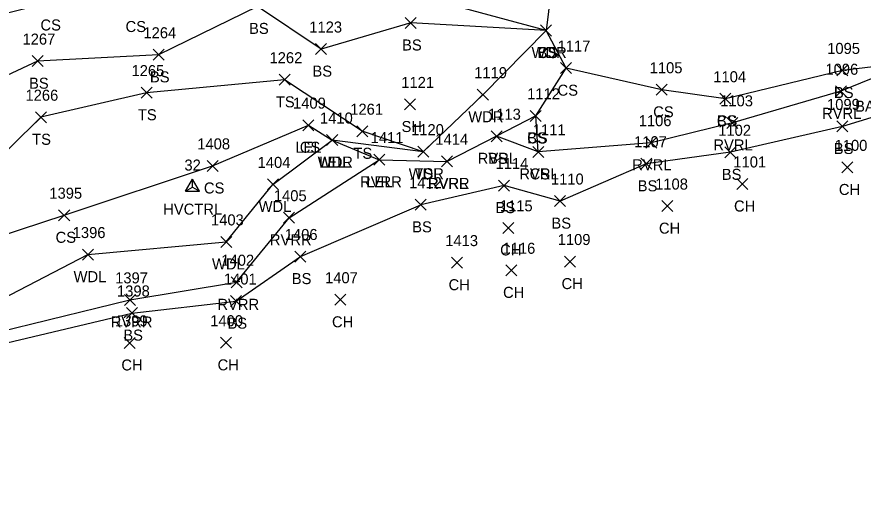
# Model space of a CAD drawing. Extents: x 1502119 to 1504100, y 606168 to 606406.
# Drawn here: x 1503856.3 to 1504009.8, y 606184.3 to 606269.9 of the extents above; entities that cross this region are included whole.
import ezdxf

# ---------------------------------------------------------------- set-up
doc = ezdxf.new("R2010")
doc.units = 0
for name, color, linetype in [('C_A', 7, 'Continuous'), ('C_I', 7, 'Continuous'), ('CPSM', 7, 'Continuous'), ('L_A', 7, 'Continuous'), ('L_C', 7, 'Continuous'), ('L_I', 7, 'Continuous'), ('L_TIC', 7, 'Continuous'), ('LARO', 7, 'Continuous'), ('LAWA', 7, 'Continuous'), ('LAWE', 7, 'Continuous'), ('LELB', 7, 'Continuous')]:
    doc.layers.add(name, color=color, linetype=linetype)

msp = doc.modelspace()

# ---------------------------------------------------------------- linework, layer by layer
at = {"layer": 'CPSM'}
for p, q in [((1503886.87, 606238.32), (1503888.12, 606240.49)), ((1503889.37, 606238.32), (1503888.12, 606240.49)), ((1503888.12, 606239.04), (1503888.12, 606240.49)), ((1503886.87, 606238.32), (1503888.12, 606239.04)), ((1503886.87, 606238.32), (1503889.37, 606238.32)), ((1503888.12, 606239.04), (1503888.12, 606239.04)), ((1503888.12, 606239.04), (1503889.37, 606238.32))]:
    msp.add_line(p, q, dxfattribs=at)
at = {"layer": 'L_TIC'}
for points in [[(1503926.72, 606267.82), (1503928.72, 606269.82)], [(1503928.72, 606267.82), (1503926.72, 606269.82)], [(1503951.28, 606266.45), (1503953.28, 606268.45)], [(1503953.28, 606266.45), (1503951.28, 606268.45)], [(1503951.28, 606266.45), (1503953.28, 606268.45)], [(1503953.28, 606266.45), (1503951.28, 606268.45)], [(1503951.28, 606266.45), (1503953.28, 606268.45)], [(1503953.28, 606266.45), (1503951.28, 606268.45)], [(1503880.96, 606262.04), (1503882.96, 606264.04)], [(1503882.96, 606262.04), (1503880.96, 606264.04)], [(1503910.45, 606263.08), (1503912.45, 606265.08)], [(1503912.45, 606263.08), (1503910.45, 606265.08)], [(1503859.02, 606260.89), (1503861.02, 606262.89)], [(1503861.02, 606260.89), (1503859.02, 606262.89)], [(1503954.93, 606259.62), (1503956.93, 606261.62)], [(1503956.93, 606259.62), (1503954.93, 606261.62)], [(1503954.93, 606259.62), (1503956.93, 606261.62)], [(1503956.93, 606259.62), (1503954.93, 606261.62)], [(1504005.07, 606259.2), (1504007.07, 606261.2)], [(1504007.07, 606259.2), (1504005.07, 606261.2)], [(1503903.84, 606257.51), (1503905.84, 606259.51)], [(1503905.84, 606257.51), (1503903.84, 606259.51)], [(1503972.29, 606255.69), (1503974.29, 606257.69)], [(1503974.29, 606255.69), (1503972.29, 606257.69)], [(1503878.8, 606255.17), (1503880.8, 606257.17)], [(1503880.8, 606255.17), (1503878.8, 606257.17)], [(1503939.81, 606254.8), (1503941.81, 606256.8)], [(1503941.81, 606254.8), (1503939.81, 606256.8)], [(1503983.83, 606254.06), (1503985.83, 606256.06)], [(1503985.83, 606254.06), (1503983.83, 606256.06)], [(1503983.83, 606254.06), (1503985.83, 606256.06)], [(1503985.83, 606254.06), (1503983.83, 606256.06)], [(1504004.8, 606255.42), (1504006.8, 606257.42)], [(1504006.8, 606255.42), (1504004.8, 606257.42)], [(1503926.57, 606253.03), (1503928.57, 606255.03)], [(1503928.57, 606253.03), (1503926.57, 606255.03)], [(1503949.41, 606250.96), (1503951.41, 606252.96)], [(1503951.41, 606250.96), (1503949.41, 606252.96)], [(1503949.41, 606250.96), (1503951.41, 606252.96)], [(1503951.41, 606250.96), (1503949.41, 606252.96)], [(1503859.62, 606250.71), (1503861.62, 606252.71)], [(1503861.62, 606250.71), (1503859.62, 606252.71)], [(1503985.09, 606249.69), (1503987.09, 606251.69)], [(1503987.09, 606249.69), (1503985.09, 606251.69)], [(1503908.15, 606249.27), (1503910.15, 606251.27)], [(1503910.15, 606249.27), (1503908.15, 606251.27)], [(1503908.15, 606249.27), (1503910.15, 606251.27)], [(1503910.15, 606249.27), (1503908.15, 606251.27)], [(1503917.92, 606248.17), (1503919.92, 606250.17)], [(1503919.92, 606248.17), (1503917.92, 606250.17)], [(1504005.05, 606249.04), (1504007.05, 606251.04)], [(1504007.05, 606249.04), (1504005.05, 606251.04)], [(1503912.47, 606246.57), (1503914.47, 606248.57)], [(1503914.47, 606246.57), (1503912.47, 606248.57)], [(1503912.47, 606246.57), (1503914.47, 606248.57)], [(1503914.47, 606246.57), (1503912.47, 606248.57)], [(1503912.47, 606246.57), (1503914.47, 606248.57)], [(1503914.47, 606246.57), (1503912.47, 606248.57)], [(1503942.31, 606247.26), (1503944.31, 606249.26)], [(1503944.31, 606247.26), (1503942.31, 606249.26)], [(1503942.31, 606247.26), (1503944.31, 606249.26)], [(1503944.31, 606247.26), (1503942.31, 606249.26)], [(1503970.36, 606246.09), (1503972.36, 606248.09)], [(1503972.36, 606246.09), (1503970.36, 606248.09)], [(1503929, 606244.46), (1503931, 606246.46)], [(1503931, 606244.46), (1503929, 606246.46)], [(1503929, 606244.46), (1503931, 606246.46)], [(1503931, 606244.46), (1503929, 606246.46)], [(1503949.87, 606244.43), (1503951.87, 606246.43)], [(1503951.87, 606244.43), (1503949.87, 606246.43)], [(1503949.87, 606244.43), (1503951.87, 606246.43)], [(1503951.87, 606244.43), (1503949.87, 606246.43)], [(1503984.73, 606244.35), (1503986.73, 606246.35)], [(1503986.73, 606244.35), (1503984.73, 606246.35)], [(1503890.76, 606241.88), (1503892.76, 606243.88)], [(1503892.76, 606241.88), (1503890.76, 606243.88)], [(1503921.02, 606243.01), (1503923.02, 606245.01)], [(1503923.02, 606243.01), (1503921.02, 606245.01)], [(1503921.02, 606243.01), (1503923.02, 606245.01)], [(1503923.02, 606243.01), (1503921.02, 606245.01)], [(1503933.31, 606242.71), (1503935.31, 606244.71)], [(1503935.31, 606242.71), (1503933.31, 606244.71)], [(1503933.31, 606242.71), (1503935.31, 606244.71)], [(1503935.31, 606242.71), (1503933.31, 606244.71)], [(1503969.47, 606242.27), (1503971.47, 606244.27)], [(1503971.47, 606242.27), (1503969.47, 606244.27)], [(1504005.93, 606241.61), (1504007.93, 606243.61)], [(1504007.93, 606241.61), (1504005.93, 606243.61)], [(1503901.71, 606238.52), (1503903.71, 606240.52)], [(1503903.71, 606238.52), (1503901.71, 606240.52)], [(1503943.68, 606238.32), (1503945.68, 606240.32)], [(1503945.68, 606238.32), (1503943.68, 606240.32)], [(1503986.9, 606238.6), (1503988.9, 606240.6)], [(1503988.9, 606238.6), (1503986.9, 606240.6)], [(1503928.55, 606234.83), (1503930.55, 606236.83)], [(1503930.55, 606234.83), (1503928.55, 606236.83)], [(1503928.55, 606234.83), (1503930.55, 606236.83)], [(1503930.55, 606234.83), (1503928.55, 606236.83)], [(1503953.82, 606235.5), (1503955.82, 606237.5)], [(1503955.82, 606235.5), (1503953.82, 606237.5)], [(1503973.29, 606234.59), (1503975.29, 606236.59)], [(1503975.29, 606234.59), (1503973.29, 606236.59)], [(1503863.84, 606232.93), (1503865.84, 606234.93)], [(1503865.84, 606232.93), (1503863.84, 606234.93)], [(1503904.66, 606232.48), (1503906.66, 606234.48)], [(1503906.66, 606232.48), (1503904.66, 606234.48)], [(1503944.46, 606230.64), (1503946.46, 606232.64)], [(1503946.46, 606230.64), (1503944.46, 606232.64)], [(1503893.25, 606228.09), (1503895.25, 606230.09)], [(1503895.25, 606228.09), (1503893.25, 606230.09)], [(1503868.14, 606225.79), (1503870.14, 606227.79)], [(1503870.14, 606225.79), (1503868.14, 606227.79)], [(1503906.7, 606225.44), (1503908.7, 606227.44)], [(1503908.7, 606225.44), (1503906.7, 606227.44)], [(1503935.11, 606224.33), (1503937.11, 606226.33)], [(1503937.11, 606224.33), (1503935.11, 606226.33)], [(1503955.61, 606224.53), (1503957.61, 606226.53)], [(1503957.61, 606224.53), (1503955.61, 606226.53)], [(1503944.99, 606222.94), (1503946.99, 606224.94)], [(1503946.99, 606222.94), (1503944.99, 606224.94)], [(1503895.13, 606220.77), (1503897.13, 606222.77)], [(1503897.13, 606220.77), (1503895.13, 606222.77)], [(1503875.78, 606217.57), (1503877.78, 606219.57)], [(1503877.78, 606217.57), (1503875.78, 606219.57)], [(1503895.03, 606217.36), (1503897.03, 606219.36)], [(1503897.03, 606217.36), (1503895.03, 606219.36)], [(1503913.95, 606217.6), (1503915.95, 606219.6)], [(1503915.95, 606217.6), (1503913.95, 606219.6)], [(1503876.12, 606215.19), (1503878.12, 606217.19)], [(1503878.12, 606215.19), (1503876.12, 606217.19)], [(1503875.73, 606209.77), (1503877.73, 606211.77)], [(1503877.73, 606209.77), (1503875.73, 606211.77)], [(1503893.2, 606209.79), (1503895.2, 606211.79)], [(1503895.2, 606209.79), (1503893.2, 606211.79)]]:
    msp.add_lwpolyline(points, dxfattribs=at)
at = {"layer": 'LARO'}
msp.add_lwpolyline([(1503909.15, 606250.27), (1503913.47, 606247.57), (1503922.02, 606244.01)], dxfattribs=at)
at = {"layer": 'LAWA'}
for points in [[(1503949.06, 606292.95), (1503954.81, 606287.72), (1503952.28, 606267.45), (1503940.81, 606255.8), (1503930, 606245.46), (1503913.47, 606247.57)], [(1503644.38, 606200.66), (1503661.82, 606197.6), (1503681.92, 606200.3), (1503697.7, 606204.96), (1503718.32, 606211.61), (1503749.72, 606205.75), (1503773.98, 606210.33), (1503804.12, 606207.66), (1503814.72, 606212.71), (1503825.12, 606213.47), (1503835.31, 606218.59), (1503851.96, 606217.91), (1503869.14, 606226.79), (1503894.25, 606229.09), (1503902.71, 606239.52), (1503913.47, 606247.57)]]:
    msp.add_lwpolyline(points, dxfattribs=at)
at = {"layer": 'LAWE'}
for points in [[(1504018.73, 606261.72), (1504005.8, 606256.42), (1503986.09, 606250.69), (1503971.36, 606247.09), (1503950.87, 606245.43), (1503943.31, 606248.26), (1503934.31, 606243.71)], [(1503614.85, 606213.1), (1503625.62, 606202.51), (1503635.42, 606197.97), (1503642.95, 606193.31), (1503660.89, 606194.04), (1503681.2, 606197.62), (1503698.42, 606201.39), (1503720.62, 606206.39), (1503749.7, 606202.44), (1503775.92, 606206.14), (1503802.08, 606202.28), (1503818.9, 606205.49), (1503835.44, 606207.89), (1503847.03, 606211.3), (1503876.78, 606218.57), (1503896.13, 606221.77), (1503905.66, 606233.48), (1503922.02, 606244.01), (1503934.31, 606243.71)]]:
    msp.add_lwpolyline(points, dxfattribs=at)
at = {"layer": 'LELB'}
for points in [[(1503954.81, 606287.72), (1503972.74, 606291.05), (1503990.82, 606291.56), (1504003.55, 606292.94), (1504011.54, 606289.1), (1504016.78, 606269.96), (1504018.73, 606261.72), (1504006.07, 606260.2), (1503984.83, 606255.06)], [(1503984.83, 606255.06), (1503973.29, 606256.69), (1503955.93, 606260.62), (1503952.28, 606267.45), (1503924.4, 606275.03), (1503909.61, 606278), (1503896.78, 606282.99), (1503877.54, 606272.17), (1503862.1, 606272.45), (1503836.9, 606266.22), (1503825.65, 606259.98), (1503818.28, 606261.16), (1503806.2, 606257.22), (1503801.33, 606241.79), (1503784.67, 606238.5), (1503757.1, 606237.25), (1503731.6, 606237.76), (1503710.27, 606237.78), (1503692.02, 606229.45), (1503676.15, 606227.07), (1503663.08, 606221.89), (1503653.08, 606223.12)], [(1503952.28, 606267.45), (1503927.72, 606268.82), (1503911.45, 606264.08), (1503899.94, 606271.83), (1503881.96, 606263.04), (1503860.02, 606261.89), (1503842.33, 606253.64), (1503837.4, 606251.84), (1503840.87, 606237.08)], [(1503950.87, 606245.43), (1503950.41, 606251.96), (1503955.93, 606260.62)], [(1503930, 606245.46), (1503918.92, 606249.17), (1503904.84, 606258.51), (1503879.8, 606256.17), (1503860.62, 606251.71), (1503849.74, 606241), (1503840.87, 606237.08), (1503831.29, 606226.33), (1503824.17, 606224.52), (1503818.07, 606222.32), (1503808.71, 606221.45), (1503786.64, 606226.93), (1503757.01, 606228.26), (1503733.84, 606223.62), (1503713.55, 606226.86), (1503694.71, 606218.05), (1503680.4, 606213.07), (1503668.25, 606209.35), (1503648.97, 606211.13)], [(1504018.69, 606253.92), (1504006.05, 606250.04), (1503985.73, 606245.35), (1503970.47, 606243.27), (1503954.82, 606236.5), (1503944.68, 606239.32), (1503929.55, 606235.83)], [(1503950.41, 606251.96), (1503943.31, 606248.26)], [(1503835.31, 606218.59), (1503848.76, 606228.68), (1503864.84, 606233.93), (1503891.76, 606242.88), (1503909.15, 606250.27)], [(1503613.71, 606211.71), (1503624.23, 606201.38), (1503628.7, 606194.41), (1503640.82, 606186.16), (1503659.4, 606184.25), (1503680.75, 606191.25), (1503695.72, 606193.45), (1503722.13, 606200.99), (1503749.25, 606197.03), (1503775.84, 606202.19), (1503801.63, 606198.61), (1503818.14, 606200.65), (1503835.99, 606205), (1503847.21, 606209.11), (1503877.12, 606216.19), (1503896.03, 606218.36), (1503907.7, 606226.44), (1503929.55, 606235.83)]]:
    msp.add_lwpolyline(points, dxfattribs=at)

# ---------------------------------------------------------------- texts
at = {"layer": 'C_A'}
msp.add_text('HVCTRL', height=2, dxfattribs=at).set_placement((1503882.81, 606234.04))
at = {"layer": 'C_I'}
msp.add_text('32', height=2, dxfattribs=at).set_placement((1503886.66, 606242.04))
at = {"layer": 'L_A'}
for s, p in [('CS', (1503860.54, 606267.45)), ('CS', (1503875.98, 606267.17)), ('BS', (1503898.39, 606266.83)), ('BS', (1503926.16, 606263.82)), ('WDR', (1503949.65, 606262.45)), ('CS', (1503950.73, 606262.45)), ('BS', (1503950.73, 606262.45)), ('BS', (1503909.89, 606259.08)), ('BS', (1503880.4, 606258.04)), ('BS', (1503858.46, 606256.89)), ('CS', (1503954.37, 606255.62)), ('CS', (1503954.37, 606255.62)), ('BS', (1504004.52, 606255.2)), ('TS', (1503903.25, 606253.51)), ('TS', (1503878.21, 606251.17)), ('CS', (1503971.73, 606251.69)), ('RVRL', (1504002.37, 606251.42)), ('WDR', (1503938.17, 606250.8)), ('CS', (1503983.27, 606250.06)), ('BS', (1503983.27, 606250.06)), ('SH', (1503926.06, 606249.03)), ('TS', (1503859.03, 606246.71)), ('CS', (1503948.85, 606246.96)), ('BS', (1503948.85, 606246.96)), ('LEL', (1503906.79, 606245.27)), ('CS', (1503907.59, 606245.27)), ('RVRL', (1503982.65, 606245.69)), ('BS', (1504004.5, 606245.04)), ('TS', (1503917.33, 606244.17)), ('BS', (1503941.76, 606243.26)), ('WDR', (1503910.84, 606242.57)), ('WDL', (1503910.89, 606242.57)), ('LEL', (1503911.11, 606242.57)), ('RVRL', (1503939.88, 606243.26)), ('RVRL', (1503967.92, 606242.09)), ('WDR', (1503927.36, 606240.46)), ('TS', (1503928.41, 606240.46)), ('RVRL', (1503947.44, 606240.43)), ('CS', (1503949.31, 606240.43)), ('BS', (1503984.17, 606240.35)), ('RVRR', (1503918.53, 606239.01)), ('LEL', (1503919.66, 606239.01)), ('RVRR', (1503930.82, 606238.71)), ('RVRL', (1503930.88, 606238.71)), ('CS', (1503890.2, 606237.88)), ('BS', (1503968.91, 606238.27)), ('CH', (1504005.42, 606237.61)), ('WDL', (1503900.13, 606234.52)), ('BS', (1503943.12, 606234.32)), ('CH', (1503986.39, 606234.6)), ('BS', (1503953.26, 606231.5)), ('BS', (1503927.99, 606230.83)), ('BS', (1503927.99, 606230.83)), ('CH', (1503972.77, 606230.59)), ('CS', (1503863.28, 606228.93)), ('RVRR', (1503902.17, 606228.48)), ('CH', (1503943.95, 606226.64)), ('WDL', (1503891.67, 606224.09)), ('WDL', (1503866.55, 606221.79)), ('BS', (1503906.14, 606221.44)), ('CH', (1503934.6, 606220.33)), ('CH', (1503955.1, 606220.53)), ('CH', (1503944.48, 606218.94)), ('RVRR', (1503892.64, 606216.77)), ('RVRR', (1503873.29, 606213.57)), ('BS', (1503894.47, 606213.36)), ('CH', (1503913.44, 606213.6)), ('BS', (1503875.57, 606211.19)), ('CH', (1503875.22, 606205.77)), ('CH', (1503892.68, 606205.79))]:
    msp.add_text(s, height=2, dxfattribs=at).set_placement(p)
at = {"layer": 'L_C'}
msp.add_text('BALWIN CREEK', height=2, dxfattribs=at).set_placement((1504008.37, 606252.72))
at = {"layer": 'L_I'}
for s, p in [('1123', (1503909.32, 606267.08)), ('1267', (1503857.28, 606264.89)), ('1264', (1503879.22, 606266.04)), ('1117', (1503954.37, 606263.62)), ('1117', (1503954.37, 606263.62)), ('1095', (1504003.3, 606263.2)), ('1262', (1503902.1, 606261.51)), ('1265', (1503877.06, 606259.17)), ('1119', (1503939.24, 606258.8)), ('1105', (1503971.09, 606259.69)), ('1096', (1504002.98, 606259.42)), ('1104', (1503982.63, 606258.06)), ('1104', (1503982.63, 606258.06)), ('1121', (1503926.01, 606257.03)), ('1266', (1503857.82, 606254.71)), ('1112', (1503948.85, 606254.96)), ('1112', (1503948.85, 606254.96)), ('1409', (1503906.37, 606253.27)), ('1409', (1503906.37, 606253.27)), ('1103', (1503983.88, 606253.69)), ('1099', (1504003.27, 606253.04)), ('1261', (1503916.75, 606252.17)), ('1113', (1503941.76, 606251.26)), ('1113', (1503941.76, 606251.26)), ('1410', (1503911.26, 606250.57)), ('1410', (1503911.26, 606250.57)), ('1410', (1503911.26, 606250.57)), ('1106', (1503969.1, 606250.09)), ('1120', (1503927.79, 606248.46)), ('1120', (1503927.79, 606248.46)), ('1111', (1503949.88, 606248.43)), ('1111', (1503949.88, 606248.43)), ('1102', (1503983.52, 606248.35)), ('1411', (1503920.46, 606247.01)), ('1411', (1503920.46, 606247.01)), ('1414', (1503932.19, 606246.71)), ('1414', (1503932.19, 606246.71)), ('1408', (1503888.99, 606245.88)), ('1107', (1503968.26, 606246.27)), ('1100', (1504004.64, 606245.61)), ('1404', (1503899.94, 606242.52)), ('1114', (1503943.12, 606242.32)), ('1101', (1503986.27, 606242.6)), ('1412', (1503927.43, 606238.83)), ('1412', (1503927.43, 606238.83)), ('1110', (1503953.17, 606239.5)), ('1108', (1503972.08, 606238.59)), ('1395', (1503862.15, 606236.93)), ('1405', (1503902.89, 606236.48)), ('1115', (1503943.9, 606234.64)), ('1403', (1503891.48, 606232.09)), ('1396', (1503866.39, 606229.79)), ('1406', (1503904.87, 606229.44)), ('1413', (1503933.99, 606228.33)), ('1109', (1503954.4, 606228.53)), ('1116', (1503944.38, 606226.94)), ('1402', (1503893.36, 606224.77)), ('1397', (1503874.09, 606221.57)), ('1401', (1503893.82, 606221.36)), ('1407', (1503912.18, 606221.6)), ('1398', (1503874.43, 606219.19)), ('1399', (1503874.03, 606213.77)), ('1400', (1503891.34, 606213.79))]:
    msp.add_text(s, height=2, dxfattribs=at).set_placement(p)

doc.saveas('drawing.dxf')
